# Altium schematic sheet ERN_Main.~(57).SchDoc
size A; SheetNumber: 1; SheetTotal: 4; SPICEModelCacheDBTNACQE: <root> / <DocumentId>DBTNACQE</DocumentId> / <CacheFrame Number="0"> / <Model Name="irf9510" Kind="CKT"> / <Text>*IRF9510  MCE  4-2-96 / *100V  4A  1.2 ohms HEXFET pkg:TO-220 2,1,3 / .SUBCKT IRF9510  10 20 40 40 / M1   1  2  3  3  DMOS L=1U W=1U / RD  10  1  .569 / RS  30  3  31M / RG  20  2  37.5 / CGS  2  3  182P / EGD 12  0  1  2  1 / VFB 14  0  0 / FFB  1  2  VFB  1 / CGD 13 14  231P / R1  13  0  1 / D1  12 13  DLIM / DDG 15 14  DCGD / R2  12 15  1 / D2  15  0  DLIM / DSD 10  3  DSUB / LS  30 40  7.5N / .MODEL DMOS PMOS (LEVEL=3 THETA=60M VMAX=208K ETA=2M VTO=-3 KP=.471) / .MODEL DCGD D (CJO=231P VJ=.6 M=.68) / .MODEL DSUB D (IS=16.6N N=1.5 RS=1.18 BV=100 CJO=327P VJ=.8 M=.42 TT=82N) / .MODEL DLIM D (IS=100U) / .ENDS IRF9510</Text> / </Model> / <Model Name="nmos" Kind="MDL"> / <Text>*Default N-Channel MOSFET / *Pinout: D,G,S / .MODEL NMOS NMOS()</Text> / </Model> / </CacheFrame> / </root>
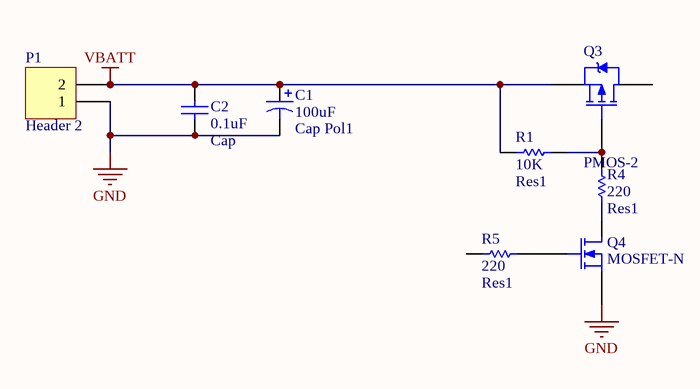
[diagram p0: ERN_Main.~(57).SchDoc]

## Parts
C1  Cap Pol1  value 100uF  [RB7.6-15]
C2  Cap  value 0.1uF  [RAD-0.3]
P1  Header 2  [HDR1X2]
Q3  PMOS-2  [TO-220AB]
Q4  MOSFET-N  [E3]
R1  Res1  value 10K  [AXIAL-0.3]
R4  Res1  value 220  [AXIAL-0.3]
R5  Res1  value 220  [AXIAL-0.3]

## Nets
GND: C1.2 C2.1 P1.1 Q4.3(S)
VBATT: C1.1 C2.2 P1.2 Q3.3(S) R1.2
NetQ3_1: Q3.1(G) R1.1 R4.1
NetQ4_1: Q4.1(D) R4.2
NetQ4_2: Q4.2(G) R5.1

Not connected (* = marked no-connect by the designer): Q3 2(D); R5 2

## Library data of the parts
C1 = Cap Pol1: Polarized Capacitor (Radial)
C2 = Cap: Capacitor
P1 = Header 2: Header, 2-Pin
Q3 = PMOS-2: P-Channel Power MOSFET; Note: Pin 4 not drawn and electrically connected to Pin 2.
Q4 = MOSFET-N: N-Channel MOSFET
R1 R4 R5 = Res1: Resistor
